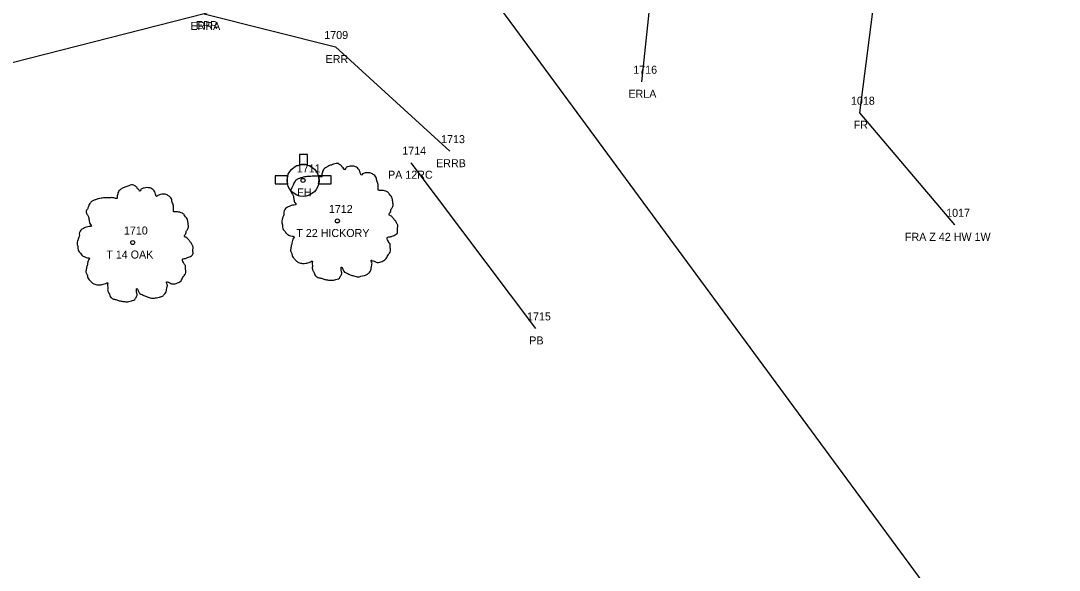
# Model space of a CAD drawing. Extents: x 1964982 to 1970452, y 1116335 to 1119906.
# Drawn here: x 1966698.6 to 1966828.3, y 1117353.3 to 1117421.9 of the extents above; entities that cross this region are included whole.
import ezdxf

# ---------------------------------------------------------------- set-up
doc = ezdxf.new("R2010")
doc.units = 0
for name, color, linetype in [('RD_EX_DR_Pipe', 7, 'Continuous'), ('RD_EX_DR_Pipe_txCode', 7, 'Continuous'), ('RD_EX_DV_Prop', 7, 'Continuous'), ('RD_EX_Fence_Other', 7, 'Continuous'), ('RD_EX_Fence_Other_txCode', 7, 'Continuous'), ('RD_EX_Road', 7, 'Continuous'), ('RD_EX_Road_txCode', 7, 'Continuous'), ('RD_EX_RW', 7, 'Continuous'), ('RD_EX_UT', 7, 'Continuous'), ('RD_EX_UT_txCode', 7, 'Continuous'), ('RD_EX_VEG', 7, 'Continuous'), ('RD_EX_VEG_txCode', 7, 'Continuous'), ('RD_SMD_Locator', 7, 'Continuous')]:
    doc.layers.add(name, color=color, linetype=linetype)

msp = doc.modelspace()

# ---------------------------------------------------------------- linework, layer by layer
at = {"layer": 'RD_EX_DR_Pipe'}
msp.add_line((1966747.3, 1117404.17), (1966762.88, 1117383.47), dxfattribs=at)
at = {"layer": 'RD_EX_DV_Prop'}
msp.add_line((1966745.73, 1117440.79), (1967101.34, 1116957.46), dxfattribs=at)
at = {"layer": 'RD_EX_Fence_Other'}
msp.add_lwpolyline([(1966815.27, 1117396.41), (1966803.38, 1117410.41), (1966806.42, 1117434.12), (1966994.62, 1117483.55), (1967088.4, 1117518.58), (1967199.69, 1117560.93), (1967210.11, 1117564.5), (1967252.59, 1117524.81)], dxfattribs=at)
at = {"layer": 'RD_EX_Road'}
for points in [[(1966776.17, 1117414.28), (1966777.92, 1117430.84), (1966787.3, 1117445.19)], [(1965729.99, 1117080.3), (1965819.77, 1117119.13), (1965907.74, 1117159.31), (1965995.36, 1117199.04), (1966039.27, 1117218.5), (1966081.24, 1117237.15), (1966124.67, 1117256.55), (1966167.66, 1117275.55), (1966211.47, 1117293.63), (1966257.79, 1117311.58), (1966302.7, 1117327.21), (1966347.9, 1117339.98), (1966394.81, 1117351.64), (1966441.56, 1117361.87), (1966488.62, 1117372.06), (1966534.91, 1117381.34), (1966581.23, 1117390.95), (1966629.53, 1117400.95), (1966675.63, 1117411.11), (1966721.68, 1117422.85), (1966766.8, 1117438.97), (1966775.75, 1117440.57)], [(1966721.5, 1117422.75), (1966737.88, 1117418.62), (1966752.16, 1117405.61)]]:
    msp.add_lwpolyline(points, dxfattribs=at)
at = {"layer": 'RD_EX_RW'}
msp.add_lwpolyline([(1965729.99, 1117080.3), (1965819.77, 1117119.13), (1965907.74, 1117159.31), (1965995.36, 1117199.04), (1966039.27, 1117218.5), (1966081.24, 1117237.15), (1966124.67, 1117256.55), (1966167.66, 1117275.55), (1966211.47, 1117293.63), (1966257.79, 1117311.58), (1966302.7, 1117327.21), (1966347.9, 1117339.98), (1966394.81, 1117351.64), (1966441.56, 1117361.87), (1966488.62, 1117372.06), (1966534.91, 1117381.34), (1966581.23, 1117390.95), (1966629.53, 1117400.95), (1966675.63, 1117411.11), (1966721.68, 1117422.85), (1966766.8, 1117438.97), (1966775.75, 1117440.57)], dxfattribs=at)
at = {"layer": 'RD_EX_UT'}
for p, q in [((1966733.38, 1117405.18), (1966733.38, 1117403.91)), ((1966734.38, 1117405.18), (1966733.38, 1117405.18)), ((1966734.38, 1117403.88), (1966734.38, 1117405.18)), ((1966731.92, 1117402.53), (1966730.37, 1117402.53)), ((1966730.37, 1117402.53), (1966730.37, 1117401.53)), ((1966737.37, 1117402.53), (1966735.76, 1117402.53)), ((1966737.37, 1117401.53), (1966737.37, 1117402.53)), ((1966730.37, 1117401.53), (1966731.89, 1117401.53)), ((1966735.79, 1117401.53), (1966737.37, 1117401.53))]:
    msp.add_line(p, q, dxfattribs=at)
for radius in [2, 0.25]:
    msp.add_circle((1966733.84, 1117401.96), radius, dxfattribs=at)
for start, end in [(74.2455, 103.2128), (163.3387, 192.315), (347.685, 16.6613)]:
    msp.add_arc((1966733.84, 1117401.96), 2, start, end, dxfattribs=at)
at = {"layer": 'RD_EX_VEG'}
for centre, radius in [((1966738.13, 1117396.89), 0.25), ((1966738.12, 1117396.87), 0.0001), ((1966712.57, 1117394.2), 0.25), ((1966712.56, 1117394.18), 0.0001)]:
    msp.add_circle(centre, radius, dxfattribs=at)
for points in [[(1966738.26, 1117404.06), (1966737.96, 1117404.08), (1966737.64, 1117403.98), (1966737.39, 1117403.88), (1966737.16, 1117403.81), (1966736.94, 1117403.71), (1966736.64, 1117403.53), (1966736.41, 1117403.33), (1966736.29, 1117403.08), (1966736.24, 1117402.86), (1966736.19, 1117402.58), (1966736.19, 1117402.41), (1966736.06, 1117402.38), (1966735.91, 1117402.41), (1966735.66, 1117402.48), (1966735.41, 1117402.48), (1966735.16, 1117402.48), (1966734.81, 1117402.46), (1966734.46, 1117402.46), (1966734.19, 1117402.41), (1966733.86, 1117402.36), (1966733.49, 1117402.23), (1966733.14, 1117402.11), (1966732.84, 1117401.86), (1966732.59, 1117401.38), (1966732.46, 1117401.03), (1966732.31, 1117400.78), (1966732.46, 1117400.33), (1966732.64, 1117399.99), (1966732.66, 1117399.79), (1966732.74, 1117399.36), (1966732.84, 1117399.14), (1966732.96, 1117398.94), (1966732.89, 1117398.91), (1966732.51, 1117398.86), (1966732.21, 1117398.76), (1966731.79, 1117398.54), (1966731.56, 1117398.31), (1966731.46, 1117397.99), (1966731.44, 1117397.64), (1966731.34, 1117397.44), (1966731.26, 1117397.16), (1966731.24, 1117397.09), (1966731.19, 1117396.76), (1966731.29, 1117396.31), (1966731.31, 1117395.96), (1966731.44, 1117395.74), (1966731.59, 1117395.56), (1966731.76, 1117395.31), (1966732.16, 1117395.09), (1966732.49, 1117394.99), (1966732.69, 1117394.96), (1966732.51, 1117394.46), (1966732.46, 1117394.11), (1966732.34, 1117393.71), (1966732.34, 1117393.64), (1966732.29, 1117393.16), (1966732.44, 1117392.84), (1966732.51, 1117392.46), (1966732.69, 1117392.24), (1966732.96, 1117391.94), (1966733.29, 1117391.71), (1966733.79, 1117391.59), (1966734.19, 1117391.61), (1966734.76, 1117391.79), (1966735.01, 1117391.86), (1966734.99, 1117391.69), (1966735.01, 1117391.31), (1966735.01, 1117390.89), (1966735.16, 1117390.56), (1966735.26, 1117390.29), (1966735.41, 1117390.04), (1966735.74, 1117389.81), (1966736.14, 1117389.74), (1966736.56, 1117389.59), (1966737.01, 1117389.51), (1966737.51, 1117389.49), (1966738.11, 1117389.64), (1966738.39, 1117389.76), (1966738.49, 1117389.94), (1966738.69, 1117390.31), (1966738.64, 1117390.54), (1966738.66, 1117391.14), (1966738.76, 1117390.96), (1966738.94, 1117390.61), (1966739.44, 1117390.31), (1966739.84, 1117390.14), (1966740.31, 1117389.99), (1966740.61, 1117389.91), (1966741.08, 1117389.99), (1966741.46, 1117390.06), (1966741.83, 1117390.19), (1966742.13, 1117390.46), (1966742.31, 1117390.74), (1966742.36, 1117391.01), (1966742.43, 1117391.39), (1966742.48, 1117391.56)], [(1966742.48, 1117391.56), (1966742.41, 1117391.74), (1966742.36, 1117391.99), (1966742.43, 1117391.96), (1966742.61, 1117391.91), (1966742.88, 1117391.79), (1966743.11, 1117391.71), (1966743.43, 1117391.74), (1966743.71, 1117391.84), (1966744.16, 1117392.11), (1966744.43, 1117392.59), (1966744.71, 1117392.99), (1966744.78, 1117393.31), (1966744.73, 1117393.54), (1966744.71, 1117394.04), (1966744.51, 1117394.29), (1966744.46, 1117394.41), (1966744.36, 1117394.81), (1966744.43, 1117394.86), (1966744.71, 1117394.91), (1966745.08, 1117395.04), (1966745.36, 1117395.16), (1966745.58, 1117395.34), (1966745.66, 1117395.56), (1966745.63, 1117395.96), (1966745.68, 1117396.36), (1966745.61, 1117396.51), (1966745.51, 1117396.66), (1966745.43, 1117396.86), (1966745.28, 1117397.01), (1966745.18, 1117397.16), (1966745.08, 1117397.26), (1966744.96, 1117397.41), (1966744.78, 1117397.54), (1966744.63, 1117397.59), (1966744.58, 1117397.74), (1966744.73, 1117397.94), (1966744.78, 1117398.04), (1966744.81, 1117398.26), (1966745.03, 1117398.61), (1966745.08, 1117399.01), (1966745.03, 1117399.44), (1966744.98, 1117399.71), (1966744.83, 1117399.99), (1966744.63, 1117400.23), (1966744.51, 1117400.41), (1966744.33, 1117400.53), (1966744.01, 1117400.66), (1966743.76, 1117400.71), (1966743.41, 1117400.71), (1966743.21, 1117400.76), (1966743.23, 1117400.81), (1966743.23, 1117400.96), (1966743.23, 1117401.23), (1966743.16, 1117401.68), (1966743.01, 1117402.18), (1966743.01, 1117402.21), (1966742.91, 1117402.46), (1966742.68, 1117402.66), (1966742.51, 1117402.76), (1966742.31, 1117402.88), (1966742.06, 1117402.91), (1966741.76, 1117402.91), (1966741.48, 1117402.86), (1966741.28, 1117402.76), (1966741.11, 1117402.63), (1966741.03, 1117402.78), (1966740.93, 1117403.08), (1966740.88, 1117403.23), (1966740.73, 1117403.41), (1966740.51, 1117403.61), (1966740.06, 1117403.73), (1966739.44, 1117403.66), (1966739.14, 1117403.46), (1966738.99, 1117403.28), (1966738.94, 1117403.41), (1966738.74, 1117403.61), (1966738.64, 1117403.78), (1966738.46, 1117403.91), (1966738.31, 1117404.01), (1966738.21, 1117404.06)], [(1966712.7, 1117401.37), (1966712.4, 1117401.4), (1966712.08, 1117401.3), (1966711.83, 1117401.2), (1966711.6, 1117401.12), (1966711.38, 1117401.02), (1966711.08, 1117400.85), (1966710.85, 1117400.65), (1966710.73, 1117400.4), (1966710.68, 1117400.17), (1966710.63, 1117399.9), (1966710.63, 1117399.72), (1966710.5, 1117399.7), (1966710.35, 1117399.72), (1966710.1, 1117399.8), (1966709.85, 1117399.8), (1966709.6, 1117399.8), (1966709.25, 1117399.77), (1966708.9, 1117399.77), (1966708.63, 1117399.72), (1966708.3, 1117399.67), (1966707.93, 1117399.55), (1966707.58, 1117399.42), (1966707.28, 1117399.17), (1966707.03, 1117398.7), (1966706.9, 1117398.35), (1966706.75, 1117398.1), (1966706.9, 1117397.65), (1966707.08, 1117397.3), (1966707.1, 1117397.1), (1966707.18, 1117396.67), (1966707.28, 1117396.45), (1966707.4, 1117396.25), (1966707.33, 1117396.22), (1966706.95, 1117396.17), (1966706.65, 1117396.07), (1966706.23, 1117395.85), (1966706, 1117395.62), (1966705.9, 1117395.3), (1966705.88, 1117394.95), (1966705.78, 1117394.75), (1966705.7, 1117394.47), (1966705.68, 1117394.4), (1966705.63, 1117394.07), (1966705.73, 1117393.62), (1966705.75, 1117393.27), (1966705.88, 1117393.05), (1966706.03, 1117392.87), (1966706.2, 1117392.62), (1966706.6, 1117392.4), (1966706.93, 1117392.3), (1966707.13, 1117392.27), (1966706.95, 1117391.77), (1966706.9, 1117391.42), (1966706.78, 1117391.02), (1966706.78, 1117390.95), (1966706.73, 1117390.48), (1966706.88, 1117390.15), (1966706.95, 1117389.78), (1966707.13, 1117389.55), (1966707.4, 1117389.25), (1966707.73, 1117389.03), (1966708.23, 1117388.9), (1966708.63, 1117388.93), (1966709.2, 1117389.1), (1966709.45, 1117389.18), (1966709.43, 1117389), (1966709.45, 1117388.63), (1966709.45, 1117388.2), (1966709.6, 1117387.88), (1966709.7, 1117387.6), (1966709.85, 1117387.35), (1966710.18, 1117387.13), (1966710.58, 1117387.05), (1966711, 1117386.9), (1966711.45, 1117386.83), (1966711.95, 1117386.8), (1966712.55, 1117386.95), (1966712.83, 1117387.08), (1966712.93, 1117387.25), (1966713.12, 1117387.63), (1966713.07, 1117387.85), (1966713.1, 1117388.45), (1966713.2, 1117388.28), (1966713.37, 1117387.93), (1966713.87, 1117387.63), (1966714.27, 1117387.45), (1966714.75, 1117387.3), (1966715.05, 1117387.23), (1966715.52, 1117387.3), (1966715.9, 1117387.38), (1966716.27, 1117387.5), (1966716.57, 1117387.78), (1966716.75, 1117388.05), (1966716.8, 1117388.33), (1966716.87, 1117388.7), (1966716.92, 1117388.88)], [(1966716.92, 1117388.88), (1966716.85, 1117389.05), (1966716.8, 1117389.3), (1966716.87, 1117389.28), (1966717.05, 1117389.23), (1966717.32, 1117389.1), (1966717.55, 1117389.03), (1966717.87, 1117389.05), (1966718.15, 1117389.15), (1966718.6, 1117389.43), (1966718.87, 1117389.9), (1966719.15, 1117390.3), (1966719.22, 1117390.63), (1966719.17, 1117390.85), (1966719.15, 1117391.35), (1966718.95, 1117391.6), (1966718.9, 1117391.72), (1966718.8, 1117392.12), (1966718.87, 1117392.17), (1966719.15, 1117392.22), (1966719.52, 1117392.35), (1966719.8, 1117392.47), (1966720.02, 1117392.65), (1966720.1, 1117392.87), (1966720.07, 1117393.27), (1966720.12, 1117393.67), (1966720.05, 1117393.82), (1966719.95, 1117393.97), (1966719.87, 1117394.17), (1966719.72, 1117394.32), (1966719.62, 1117394.47), (1966719.52, 1117394.57), (1966719.4, 1117394.72), (1966719.22, 1117394.85), (1966719.07, 1117394.9), (1966719.02, 1117395.05), (1966719.17, 1117395.25), (1966719.22, 1117395.35), (1966719.25, 1117395.57), (1966719.47, 1117395.92), (1966719.52, 1117396.32), (1966719.47, 1117396.75), (1966719.42, 1117397.02), (1966719.27, 1117397.3), (1966719.07, 1117397.55), (1966718.95, 1117397.72), (1966718.77, 1117397.85), (1966718.45, 1117397.97), (1966718.2, 1117398.02), (1966717.85, 1117398.02), (1966717.65, 1117398.07), (1966717.67, 1117398.12), (1966717.67, 1117398.27), (1966717.67, 1117398.55), (1966717.6, 1117399), (1966717.45, 1117399.5), (1966717.45, 1117399.52), (1966717.35, 1117399.77), (1966717.12, 1117399.97), (1966716.95, 1117400.07), (1966716.75, 1117400.2), (1966716.5, 1117400.22), (1966716.2, 1117400.22), (1966715.92, 1117400.17), (1966715.72, 1117400.07), (1966715.55, 1117399.95), (1966715.47, 1117400.1), (1966715.37, 1117400.4), (1966715.32, 1117400.55), (1966715.17, 1117400.72), (1966714.95, 1117400.92), (1966714.5, 1117401.05), (1966713.87, 1117400.97), (1966713.57, 1117400.77), (1966713.42, 1117400.6), (1966713.37, 1117400.72), (1966713.17, 1117400.92), (1966713.07, 1117401.1), (1966712.9, 1117401.22), (1966712.75, 1117401.32), (1966712.65, 1117401.37)]]:
    msp.add_spline(points, degree=3, dxfattribs=at)
at = {"layer": 'RD_SMD_Locator'}
for centre in [(1966737.88, 1117418.62), (1966776.17, 1117414.28), (1966803.38, 1117410.41), (1966752.16, 1117405.61), (1966747.3, 1117404.17), (1966815.27, 1117396.41), (1966762.88, 1117383.47)]:
    msp.add_circle(centre, 0.001, dxfattribs=at)

# ---------------------------------------------------------------- texts
at = {"layer": 'RD_EX_DR_Pipe_txCode'}
for s, p in [('1714', (1966746.24, 1117405.17)), ('PA 12RC', (1966744.46, 1117402.17)), ('1715', (1966761.82, 1117384.47)), ('PB', (1966762.1, 1117381.47))]:
    msp.add_text(s, height=1, dxfattribs=at).set_placement(p)
at = {"layer": 'RD_EX_Fence_Other_txCode'}
for s, p in [('1018', (1966802.28, 1117411.41)), ('FR', (1966802.62, 1117408.41)), ('1017', (1966814.17, 1117397.41)), ('FRA Z 42 HW 1W', (1966809.02, 1117394.41))]:
    msp.add_text(s, height=1, dxfattribs=at).set_placement(p)
at = {"layer": 'RD_EX_Road_txCode'}
for s, p in [('ERRA', (1966719.78, 1117420.75)), ('EPR', (1966720.45, 1117420.85)), ('EPR', (1966720.45, 1117420.85)), ('1709', (1966736.5, 1117419.62)), ('ERR', (1966736.66, 1117416.62)), ('1716', (1966775.09, 1117415.28)), ('ERLA', (1966774.48, 1117412.28)), ('1713', (1966751.09, 1117406.61)), ('ERRB', (1966750.46, 1117403.61))]:
    msp.add_text(s, height=1, dxfattribs=at).set_placement(p)
at = {"layer": 'RD_EX_UT_txCode'}
for s, p in [('1711', (1966733.06, 1117402.96)), ('FH', (1966733.11, 1117399.96))]:
    msp.add_text(s, height=1, dxfattribs=at).set_placement(p)
at = {"layer": 'RD_EX_VEG_txCode'}
for s, p in [('1712', (1966737.07, 1117397.89)), ('1710', (1966711.47, 1117395.2)), ('T 22 HICKORY', (1966733, 1117394.89)), ('T 14 OAK', (1966709.27, 1117392.2))]:
    msp.add_text(s, height=1, dxfattribs=at).set_placement(p)

doc.saveas('drawing.dxf')
